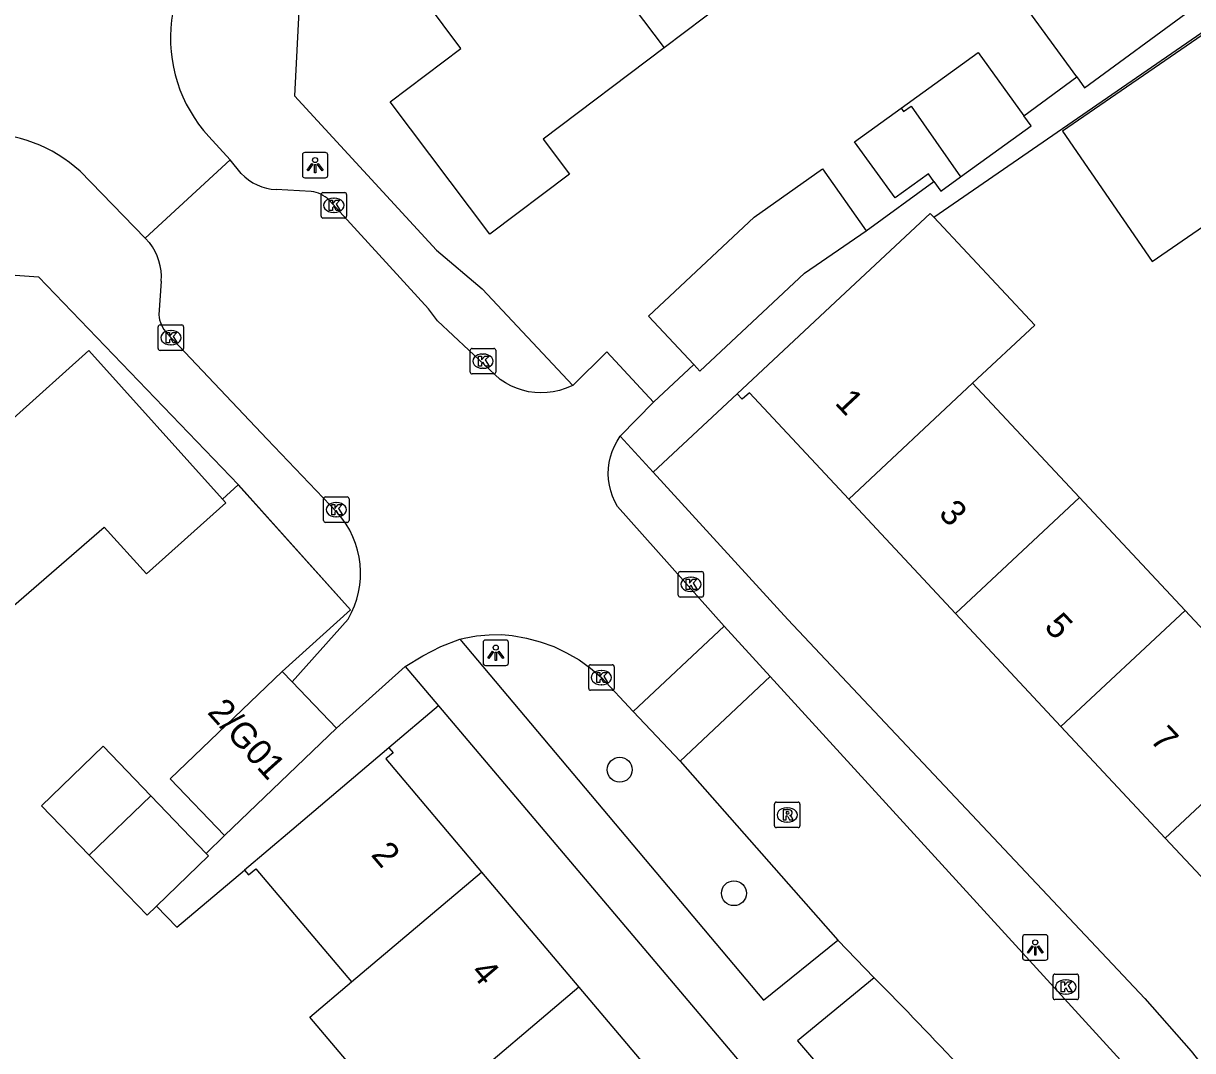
# Model space of a CAD drawing. Extents: x 157466 to 158888, y 383063 to 384677.
# Drawn here: x 158056 to 158101.94, y 383679.09 to 383719.45 of the extents above; entities that cross this region are included whole.
import ezdxf

# ---------------------------------------------------------------- set-up
doc = ezdxf.new("R2010")
doc.units = 0
for name, color, linetype in [('IMGEO_Boom', 7, 'Continuous'), ('IMGEO_Kolk', 7, 'Continuous'), ('IMGEO_Lichtpunt', 7, 'Continuous'), ('IMGEO_Muur', 7, 'Continuous'), ('IMGEO_Pand', 7, 'Continuous'), ('IMGEO_Pand_nummerreeks', 7, 'Continuous'), ('IMGEO_Rijbaan_lokaal_open', 7, 'Continuous'), ('IMGEO_Rioolput', 7, 'Continuous'), ('IMGEO_Voetpad_open', 7, 'Continuous')]:
    doc.layers.add(name, color=color, linetype=linetype)

msp = doc.modelspace()

# ---------------------------------------------------------------- linework, layer by layer
at = {"layer": 'IMGEO_Boom'}
for centre in [(158079.433, 383690.12), (158083.92, 383685.27)]:
    msp.add_circle(centre, 0.489, dxfattribs=at)
at = {"layer": 'IMGEO_Kolk'}
for p, q in [((158067.699, 383711.873), (158067.699, 383712.725)), ((158067.774, 383712.799), (158068.626, 383712.799)), ((158068.7, 383712.725), (158068.7, 383711.873)), ((158068.187, 383712.579), (158068.212, 383712.579)), ((158068.21, 383712.019), (158068.185, 383712.019)), ((158068.626, 383711.799), (158067.774, 383711.799)), ((158061.297, 383706.673), (158061.297, 383707.525)), ((158061.372, 383707.599), (158062.224, 383707.599)), ((158061.785, 383707.379), (158061.81, 383707.379)), ((158062.298, 383707.525), (158062.298, 383706.673)), ((158061.808, 383706.819), (158061.783, 383706.819)), ((158062.224, 383706.599), (158061.372, 383706.599)), ((158073.559, 383705.748), (158073.559, 383706.6)), ((158073.634, 383706.674), (158074.486, 383706.674)), ((158074.047, 383706.454), (158074.072, 383706.454)), ((158074.56, 383706.6), (158074.56, 383705.748)), ((158074.07, 383705.894), (158074.045, 383705.894)), ((158074.486, 383705.674), (158073.634, 383705.674)), ((158067.87, 383700.838), (158068.722, 383700.838)), ((158067.795, 383699.912), (158067.795, 383700.764)), ((158068.283, 383700.618), (158068.308, 383700.618)), ((158068.796, 383700.764), (158068.796, 383699.912)), ((158068.306, 383700.058), (158068.281, 383700.058)), ((158068.722, 383699.838), (158067.87, 383699.838)), ((158081.729, 383696.981), (158081.729, 383697.833)), ((158081.804, 383697.907), (158082.656, 383697.907)), ((158082.217, 383697.687), (158082.242, 383697.687)), ((158082.73, 383697.833), (158082.73, 383696.981)), ((158082.24, 383697.127), (158082.215, 383697.127)), ((158082.656, 383696.907), (158081.804, 383696.907)), ((158078.213, 383693.317), (158078.213, 383694.169)), ((158078.288, 383694.243), (158079.14, 383694.243)), ((158078.701, 383694.023), (158078.726, 383694.023)), ((158079.214, 383694.169), (158079.214, 383693.317)), ((158078.724, 383693.463), (158078.699, 383693.463)), ((158079.14, 383693.243), (158078.288, 383693.243)), ((158096.46, 383681.163), (158096.46, 383682.015)), ((158096.535, 383682.089), (158097.387, 383682.089)), ((158097.461, 383682.015), (158097.461, 383681.163)), ((158096.948, 383681.869), (158096.973, 383681.869)), ((158097.387, 383681.089), (158096.535, 383681.089)), ((158096.971, 383681.309), (158096.946, 383681.309))]:
    msp.add_line(p, q, dxfattribs=at)
for points in [[(158067.699, 383711.873), (158067.699, 383712.725)], [(158067.774, 383712.799), (158068.626, 383712.799)], [(158068.7, 383712.725), (158068.7, 383711.873)], [(158068.02, 383712.499), (158068.143, 383712.499), (158068.143, 383712.348), (158068.273, 383712.499), (158068.437, 383712.499), (158068.291, 383712.348), (158068.444, 383712.099), (158068.292, 383712.099), (158068.207, 383712.263), (158068.143, 383712.196), (158068.143, 383712.099), (158068.02, 383712.099), (158068.02, 383712.499)], [(158068.626, 383711.799), (158067.774, 383711.799)], [(158061.297, 383706.673), (158061.297, 383707.525)], [(158061.372, 383707.599), (158062.224, 383707.599)], [(158061.618, 383707.299), (158061.741, 383707.299), (158061.741, 383707.148), (158061.871, 383707.299), (158062.035, 383707.299), (158061.889, 383707.148), (158062.042, 383706.899), (158061.89, 383706.899), (158061.805, 383707.063), (158061.741, 383706.996), (158061.741, 383706.899), (158061.618, 383706.899), (158061.618, 383707.299)], [(158062.298, 383707.525), (158062.298, 383706.673)], [(158062.224, 383706.599), (158061.372, 383706.599)], [(158073.559, 383705.748), (158073.559, 383706.6)], [(158073.634, 383706.674), (158074.486, 383706.674)], [(158073.88, 383706.374), (158074.003, 383706.374), (158074.003, 383706.223), (158074.133, 383706.374), (158074.297, 383706.374), (158074.151, 383706.223), (158074.304, 383705.974), (158074.152, 383705.974), (158074.067, 383706.138), (158074.003, 383706.071), (158074.003, 383705.974), (158073.88, 383705.974), (158073.88, 383706.374)], [(158074.56, 383706.6), (158074.56, 383705.748)], [(158074.486, 383705.674), (158073.634, 383705.674)], [(158067.87, 383700.838), (158068.722, 383700.838)], [(158067.795, 383699.912), (158067.795, 383700.764)], [(158068.116, 383700.538), (158068.239, 383700.538), (158068.239, 383700.387), (158068.369, 383700.538), (158068.533, 383700.538), (158068.387, 383700.387), (158068.54, 383700.138), (158068.388, 383700.138), (158068.303, 383700.302), (158068.239, 383700.235), (158068.239, 383700.138), (158068.116, 383700.138), (158068.116, 383700.538)], [(158068.796, 383700.764), (158068.796, 383699.912)], [(158068.722, 383699.838), (158067.87, 383699.838)], [(158081.729, 383696.981), (158081.729, 383697.833)], [(158081.804, 383697.907), (158082.656, 383697.907)], [(158082.05, 383697.607), (158082.173, 383697.607), (158082.173, 383697.456), (158082.303, 383697.607), (158082.467, 383697.607), (158082.321, 383697.456), (158082.474, 383697.207), (158082.322, 383697.207), (158082.237, 383697.371), (158082.173, 383697.304), (158082.173, 383697.207), (158082.05, 383697.207), (158082.05, 383697.607)], [(158082.73, 383697.833), (158082.73, 383696.981)], [(158082.656, 383696.907), (158081.804, 383696.907)], [(158078.213, 383693.317), (158078.213, 383694.169)], [(158078.288, 383694.243), (158079.14, 383694.243)], [(158078.534, 383693.943), (158078.657, 383693.943), (158078.657, 383693.792), (158078.787, 383693.943), (158078.951, 383693.943), (158078.805, 383693.792), (158078.958, 383693.543), (158078.806, 383693.543), (158078.721, 383693.707), (158078.657, 383693.64), (158078.657, 383693.543), (158078.534, 383693.543), (158078.534, 383693.943)], [(158079.214, 383694.169), (158079.214, 383693.317)], [(158079.14, 383693.243), (158078.288, 383693.243)], [(158096.46, 383681.163), (158096.46, 383682.015)], [(158096.535, 383682.089), (158097.387, 383682.089)], [(158097.461, 383682.015), (158097.461, 383681.163)], [(158096.781, 383681.789), (158096.904, 383681.789), (158096.904, 383681.638), (158097.034, 383681.789), (158097.198, 383681.789), (158097.052, 383681.638), (158097.205, 383681.389), (158097.053, 383681.389), (158096.968, 383681.553), (158096.904, 383681.486), (158096.904, 383681.389), (158096.781, 383681.389), (158096.781, 383681.789)], [(158097.387, 383681.089), (158096.535, 383681.089)]]:
    msp.add_lwpolyline(points, dxfattribs=at)
for centre, start, end in [((158067.776, 383712.723), 91.552, 178.448), ((158067.776, 383712.723), 91.552, 178.448), ((158068.624, 383712.723), 1.552, 88.448), ((158068.624, 383712.723), 1.552, 88.448), ((158067.776, 383711.875), 181.552, 268.448), ((158067.776, 383711.875), 181.552, 268.448), ((158068.624, 383711.875), 271.552, 358.448), ((158068.624, 383711.875), 271.552, 358.448), ((158061.374, 383707.523), 91.552, 178.448), ((158061.374, 383707.523), 91.552, 178.448), ((158062.222, 383707.523), 1.552, 88.448), ((158062.222, 383707.523), 1.552, 88.448), ((158061.374, 383706.675), 181.552, 268.448), ((158061.374, 383706.675), 181.552, 268.448), ((158062.222, 383706.675), 271.552, 358.448), ((158062.222, 383706.675), 271.552, 358.448), ((158073.636, 383706.598), 91.552, 178.448), ((158073.636, 383706.598), 91.552, 178.448), ((158074.484, 383706.598), 1.552, 88.448), ((158074.484, 383706.598), 1.552, 88.448), ((158073.636, 383705.75), 181.552, 268.448), ((158073.636, 383705.75), 181.552, 268.448), ((158074.484, 383705.75), 271.552, 358.448), ((158074.484, 383705.75), 271.552, 358.448), ((158067.872, 383700.762), 91.552, 178.448), ((158067.872, 383700.762), 91.552, 178.448), ((158068.72, 383700.762), 1.552, 88.448), ((158068.72, 383700.762), 1.552, 88.448), ((158067.872, 383699.914), 181.552, 268.448), ((158067.872, 383699.914), 181.552, 268.448), ((158068.72, 383699.914), 271.552, 358.448), ((158068.72, 383699.914), 271.552, 358.448), ((158081.806, 383697.831), 91.552, 178.448), ((158081.806, 383697.831), 91.552, 178.448), ((158082.654, 383697.831), 1.552, 88.448), ((158082.654, 383697.831), 1.552, 88.448), ((158081.806, 383696.983), 181.552, 268.448), ((158081.806, 383696.983), 181.552, 268.448), ((158082.654, 383696.983), 271.552, 358.448), ((158082.654, 383696.983), 271.552, 358.448), ((158078.29, 383694.167), 91.552, 178.448), ((158078.29, 383694.167), 91.552, 178.448), ((158079.138, 383694.167), 1.552, 88.448), ((158079.138, 383694.167), 1.552, 88.448), ((158078.29, 383693.319), 181.552, 268.448), ((158078.29, 383693.319), 181.552, 268.448), ((158079.138, 383693.319), 271.552, 358.448), ((158079.138, 383693.319), 271.552, 358.448), ((158096.537, 383682.013), 91.552, 178.448), ((158096.537, 383682.013), 91.552, 178.448), ((158097.385, 383682.013), 1.552, 88.448), ((158097.385, 383682.013), 1.552, 88.448), ((158096.537, 383681.165), 181.552, 268.448), ((158096.537, 383681.165), 181.552, 268.448), ((158097.385, 383681.165), 271.552, 358.448), ((158097.385, 383681.165), 271.552, 358.448)]:
    msp.add_arc(centre, 0.0765, start, end, dxfattribs=at)
for centre, major_axis, ratio, start_param, end_param in [((158068.186, 383712.299), (-0.387, 0.002), 0.722429, 4.712389, 7.853982), ((158068.211, 383712.299), (-0.39, 0.002), 0.717154, 1.570796, 4.712389), ((158061.784, 383707.099), (-0.387, 0.002), 0.722429, 4.712389, 7.853982), ((158061.809, 383707.099), (-0.39, 0.002), 0.717154, 1.570796, 4.712389), ((158074.046, 383706.174), (-0.387, 0.002), 0.722429, 4.712389, 7.853982), ((158074.071, 383706.174), (-0.39, 0.002), 0.717154, 1.570796, 4.712389), ((158068.282, 383700.338), (-0.387, 0.002), 0.722429, 4.712389, 7.853982), ((158068.307, 383700.338), (-0.39, 0.002), 0.717154, 1.570796, 4.712389), ((158082.216, 383697.407), (-0.387, 0.002), 0.722429, 4.712389, 7.853982), ((158082.241, 383697.407), (-0.39, 0.002), 0.717154, 1.570796, 4.712389), ((158078.7, 383693.743), (-0.387, 0.002), 0.722429, 4.712389, 7.853982), ((158078.725, 383693.743), (-0.39, 0.002), 0.717154, 1.570796, 4.712389), ((158096.947, 383681.589), (-0.387, 0.002), 0.722429, 4.712389, 7.853982), ((158096.972, 383681.589), (-0.39, 0.002), 0.717154, 1.570796, 4.712389)]:
    msp.add_ellipse(centre, major_axis=major_axis, ratio=ratio, start_param=start_param, end_param=end_param, dxfattribs=at)
at = {"layer": 'IMGEO_Lichtpunt'}
for p, q in [((158066.964, 383714.279), (158066.964, 383713.472)), ((158066.964, 383714.279), (158066.964, 383713.472)), ((158067.866, 383714.374), (158067.058, 383714.374)), ((158067.866, 383714.374), (158067.058, 383714.374)), ((158067.96, 383713.472), (158067.96, 383714.279)), ((158067.96, 383713.472), (158067.96, 383714.279)), ((158067.058, 383713.378), (158067.866, 383713.378)), ((158067.058, 383713.378), (158067.866, 383713.378)), ((158074.062, 383695.121), (158074.062, 383694.314)), ((158074.062, 383695.121), (158074.062, 383694.314)), ((158074.964, 383695.216), (158074.156, 383695.216)), ((158074.964, 383695.216), (158074.156, 383695.216)), ((158075.058, 383694.314), (158075.058, 383695.121)), ((158075.058, 383694.314), (158075.058, 383695.121)), ((158074.156, 383694.22), (158074.964, 383694.22)), ((158074.156, 383694.22), (158074.964, 383694.22)), ((158095.262, 383683.541), (158095.262, 383682.734)), ((158095.262, 383683.541), (158095.262, 383682.734)), ((158096.164, 383683.636), (158095.356, 383683.636)), ((158096.164, 383683.636), (158095.356, 383683.636)), ((158096.258, 383682.734), (158096.258, 383683.541)), ((158096.258, 383682.734), (158096.258, 383683.541)), ((158095.356, 383682.64), (158096.164, 383682.64)), ((158095.356, 383682.64), (158096.164, 383682.64))]:
    msp.add_line(p, q, dxfattribs=at)
for points in [[(158067.338, 383713.943), (158067.377, 383713.915), (158067.189, 383713.653), (158067.151, 383713.68), (158067.338, 383713.943)], [(158067.44, 383713.895), (158067.487, 383713.895), (158067.487, 383713.573), (158067.44, 383713.573), (158067.44, 383713.895)], [(158067.55, 383713.915), (158067.588, 383713.942), (158067.775, 383713.68), (158067.736, 383713.652), (158067.55, 383713.915)], [(158074.436, 383694.785), (158074.475, 383694.757), (158074.287, 383694.495), (158074.249, 383694.522), (158074.436, 383694.785)], [(158074.538, 383694.737), (158074.585, 383694.737), (158074.585, 383694.415), (158074.538, 383694.415), (158074.538, 383694.737)], [(158074.648, 383694.757), (158074.686, 383694.784), (158074.873, 383694.522), (158074.834, 383694.494), (158074.648, 383694.757)], [(158095.636, 383683.205), (158095.675, 383683.177), (158095.487, 383682.915), (158095.449, 383682.942), (158095.636, 383683.205)], [(158095.738, 383683.157), (158095.785, 383683.157), (158095.785, 383682.835), (158095.738, 383682.835), (158095.738, 383683.157)], [(158095.848, 383683.177), (158095.886, 383683.204), (158096.073, 383682.942), (158096.034, 383682.914), (158095.848, 383683.177)]]:
    msp.add_lwpolyline(points, dxfattribs=at)
for centre in [(158067.463, 383714.077), (158074.561, 383694.919), (158095.761, 383683.339)]:
    msp.add_circle(centre, 0.0994, dxfattribs=at)
for centre, start, end in [((158067.058, 383714.279), 90, 180), ((158067.058, 383714.279), 90, 180), ((158067.866, 383714.279), 0, 90), ((158067.866, 383714.279), 0, 90), ((158067.058, 383713.472), 180, 270), ((158067.058, 383713.472), 180, 270), ((158067.866, 383713.472), 270, 0), ((158067.866, 383713.472), 270, 360), ((158074.156, 383695.121), 90, 180), ((158074.156, 383695.121), 90, 180), ((158074.964, 383695.121), 0, 90), ((158074.964, 383695.121), 0, 90), ((158074.156, 383694.314), 180, 270), ((158074.156, 383694.314), 180, 270), ((158074.964, 383694.314), 270, 0), ((158074.964, 383694.314), 270, 360), ((158095.356, 383683.541), 90, 180), ((158095.356, 383683.541), 90, 180), ((158096.164, 383683.541), 0, 90), ((158096.164, 383683.541), 0, 90), ((158095.356, 383682.734), 180, 270), ((158095.356, 383682.734), 180, 270), ((158096.164, 383682.734), 270, 0), ((158096.164, 383682.734), 270, 360)]:
    msp.add_arc(centre, 0.0946, start, end, dxfattribs=at)
at = {"layer": 'IMGEO_Muur'}
for points in [[(158074.025, 383709.017), (158077.584, 383705.224)], [(158063.821, 383700.757), (158064.446, 383701.318)], [(158064.446, 383701.318), (158068.858, 383696.409)], [(158066.165, 383693.981), (158068.858, 383696.409)]]:
    msp.add_lwpolyline(points, dxfattribs=at)
at = {"layer": 'IMGEO_Pand'}
for points in [[(158081.173, 383718.488), (158076.419, 383714.899), (158077.455, 383713.526), (158074.328, 383711.165), (158070.408, 383716.358), (158073.195, 383718.462), (158071.797, 383720.314), (158072.106, 383720.547), (158072.365, 383720.203), (158077.158, 383723.821)], [(158077.158, 383723.821), (158081.173, 383718.488)], [(158097.388, 383717.341), (158095.503, 383719.92), (158099.684, 383722.976)], [(158097.388, 383717.341), (158097.697, 383716.918), (158101.878, 383719.973), (158099.684, 383722.976)], [(158085.977, 383722.114), (158081.173, 383718.488)], [(158102.524, 383719.13), (158096.827, 383715.205), (158100.352, 383710.087), (158103.342, 383712.147)], [(158090.491, 383716.118), (158093.515, 383718.301), (158095.307, 383715.819)], [(158091.776, 383713.239), (158091.562, 383713.535), (158090.251, 383712.589), (158088.659, 383714.795), (158090.491, 383716.118)], [(158090.491, 383716.118), (158090.589, 383715.988), (158090.888, 383716.196), (158092.816, 383713.412)], [(158092.816, 383713.412), (158095.596, 383715.419), (158095.307, 383715.819)], [(158082.342, 383706.039), (158080.56, 383707.946), (158084.714, 383711.826), (158087.401, 383713.728), (158089.119, 383711.297)], [(158091.776, 383713.239), (158092.05, 383712.859), (158092.816, 383713.412)], [(158091.772, 383711.829), (158091.632, 383711.98), (158089.485, 383709.977), (158087.7, 383708.309), (158084.045, 383704.896)], [(158093.299, 383705.306), (158095.737, 383707.585), (158091.772, 383711.829)], [(158082.342, 383706.039), (158082.578, 383705.786), (158086.698, 383709.634), (158089.119, 383711.297)], [(158054.533, 383695.63), (158059.181, 383699.651), (158060.834, 383697.812), (158063.954, 383700.608), (158063.821, 383700.757), (158058.573, 383706.595), (158055.594, 383703.926), (158054.197, 383705.48), (158053.956, 383705.264), (158054.22, 383704.97), (158049.774, 383701.125)], [(158088.43, 383700.755), (158084.527, 383704.934), (158084.25, 383704.676), (158084.045, 383704.896)], [(158088.43, 383700.755), (158093.299, 383705.306)], [(158097.496, 383700.816), (158093.299, 383705.306)], [(158092.625, 383696.263), (158097.496, 383700.816)], [(158101.644, 383696.379), (158097.496, 383700.816)], [(158092.625, 383696.263), (158088.43, 383700.755)], [(158096.77, 383691.825), (158092.625, 383696.263)], [(158101.644, 383696.379), (158096.77, 383691.825)], [(158105.745, 383691.992), (158101.644, 383696.379)], [(158066.165, 383693.981), (158061.766, 383689.76), (158063.904, 383687.532)], [(158066.165, 383693.981), (158066.557, 383693.572)], [(158066.557, 383693.572), (158068.304, 383691.753)], [(158063.904, 383687.532), (158068.304, 383691.753)], [(158100.869, 383687.435), (158096.77, 383691.825)], [(158100.869, 383687.435), (158105.745, 383691.992)], [(158061.011, 383689.092), (158059.139, 383691.042), (158056.713, 383688.701), (158058.585, 383686.761)], [(158070.36, 383690.983), (158066.544, 383687.753), (158064.686, 383686.181)], [(158070.36, 383690.983), (158070.525, 383690.787), (158070.237, 383690.543), (158074, 383686.097)], [(158058.585, 383686.761), (158061.011, 383689.092)], [(158063.179, 383686.834), (158061.011, 383689.092)], [(158105.049, 383682.96), (158100.869, 383687.435)], [(158058.585, 383686.761), (158060.862, 383684.402), (158061.232, 383684.759)], [(158063.179, 383686.834), (158063.277, 383686.732), (158061.232, 383684.759)], [(158064.686, 383686.181), (158064.846, 383685.992), (158065.131, 383686.233), (158068.897, 383681.783)], [(158068.897, 383681.783), (158074, 383686.097)], [(158074, 383686.097), (158077.829, 383681.572)], [(158072.726, 383677.258), (158071.078, 383675.88), (158067.259, 383680.398), (158068.897, 383681.783)], [(158077.829, 383681.572), (158072.726, 383677.258)], [(158077.829, 383681.572), (158081.783, 383676.9)]]:
    msp.add_lwpolyline(points, dxfattribs=at)
at = {"layer": 'IMGEO_Rijbaan_lokaal_open'}
for points in [[(158064.124, 383714.09), (158063.283, 383715.004)], [(158060.786, 383711.008), (158064.124, 383714.09)], [(158064.56, 383713.552), (158064.124, 383714.09)], [(158058.232, 383713.633), (158060.786, 383711.008)], [(158067.311, 383712.842), (158065.937, 383712.913)], [(158077.584, 383705.224), (158077.52, 383705.193), (158077.295, 383705.098), (158077.062, 383705.024), (158076.823, 383704.971), (158076.581, 383704.939), (158076.336, 383704.929), (158076.092, 383704.941), (158075.85, 383704.975), (158075.612, 383705.03), (158075.379, 383705.107), (158075.155, 383705.203), (158074.94, 383705.32), (158074.736, 383705.455), (158072.279, 383707.764), (158071.914, 383708.233), (158068.01, 383712.506)], [(158060.786, 383711.008), (158060.962, 383710.83)], [(158061.42, 383709.32), (158061.322, 383707.998)], [(158061.65, 383707.256), (158065.583, 383703.103), (158068.326, 383700.226)], [(158077.584, 383705.224), (158078.924, 383706.544), (158080.76, 383704.561)], [(158079.451, 383703.221), (158080.76, 383704.561)], [(158083.532, 383695.764), (158079.347, 383700.464), (158079.239, 383700.662), (158079.15, 383700.868), (158079.079, 383701.081), (158079.028, 383701.299), (158078.996, 383701.522), (158078.985, 383701.746), (158078.993, 383701.97), (158079.022, 383702.193), (158079.07, 383702.412), (158079.138, 383702.627), (158079.224, 383702.834), (158079.329, 383703.032), (158079.451, 383703.221)], [(158068.759, 383696.04), (158066.557, 383693.572)], [(158079.964, 383692.414), (158083.532, 383695.764)], [(158085.347, 383693.787), (158083.532, 383695.764)], [(158073.153, 383695.248), (158073.321, 383695.29), (158073.811, 383695.381), (158074.307, 383695.428), (158074.806, 383695.43), (158075.212, 383695.391), (158075.767, 383695.295), (158076.31, 383695.15), (158076.838, 383694.957), (158077.347, 383694.717), (158077.833, 383694.433), (158078.291, 383694.107), (158078.718, 383693.741), (158079.964, 383692.414)], [(158071.006, 383694.181), (158071.692, 383694.602), (158072.408, 383694.958), (158073.153, 383695.248)], [(158068.304, 383691.753), (158071.006, 383694.181)], [(158085.347, 383693.787), (158081.806, 383690.454)], [(158117.353, 383655.647), (158105.457, 383671.597), (158103.101, 383674.336), (158085.347, 383693.787)], [(158081.806, 383690.454), (158079.964, 383692.414)], [(158081.806, 383690.454), (158088.008, 383683.429)], [(158088.008, 383683.429), (158089.434, 383681.946)]]:
    msp.add_lwpolyline(points, dxfattribs=at)
for centre, radius, start, end in [((158067.516, 383718.875), 5.736, 123.6171, 222.4461), ((158054.425, 383709.481), 5.633, 47.4872, 91.4484), ((158066.03, 383714.916), 2.005, 222.8619, 267.3506), ((158067.148, 383711.608), 1.245, 46.1731, 82.4809), ((158059.209, 383709.474), 2.216, 356.0163, 37.73), ((158062.546, 383708.096), 1.228, 184.5559, 223.1396), ((158065.721, 383697.841), 3.531, 329.3328, 42.4785), ((157977.199, 383570.714), 158.017, 42.92697, 44.74268)]:
    msp.add_arc(centre, radius, start, end, dxfattribs=at)
at = {"layer": 'IMGEO_Rioolput'}
for p, q in [((158085.588, 383688.847), (158086.44, 383688.847)), ((158085.513, 383687.921), (158085.513, 383688.773)), ((158086.001, 383688.627), (158086.026, 383688.627)), ((158086.514, 383688.773), (158086.514, 383687.921)), ((158086.024, 383688.067), (158085.999, 383688.067)), ((158086.44, 383687.847), (158085.588, 383687.847))]:
    msp.add_line(p, q, dxfattribs=at)
for points in [[(158085.588, 383688.847), (158086.44, 383688.847)], [(158085.513, 383687.921), (158085.513, 383688.773)], [(158086.102, 383688.545), (158085.85, 383688.547), (158085.85, 383688.147)], [(158086.028, 383688.466), (158085.974, 383688.466), (158085.974, 383688.385)], [(158085.974, 383688.385), (158086.026, 383688.385)], [(158086.514, 383688.773), (158086.514, 383687.921)], [(158085.85, 383688.147), (158085.974, 383688.147), (158085.974, 383688.309), (158085.985, 383688.309)], [(158086.032, 383688.28), (158086.103, 383688.147), (158086.243, 383688.147), (158086.178, 383688.273)], [(158086.44, 383687.847), (158085.588, 383687.847)]]:
    msp.add_lwpolyline(points, dxfattribs=at)
for centre, radius, start, end in [((158085.59, 383688.771), 0.0765, 91.552, 178.448), ((158085.59, 383688.771), 0.0765, 91.552, 178.448), ((158086.438, 383688.771), 0.0765, 1.552, 88.448), ((158086.438, 383688.771), 0.0765, 1.552, 88.448), ((158086.01, 383688.574), 0.19, 274.7715, 282.9687), ((158086.034, 383688.37), 0.0964, 77.0061, 93.1865), ((158086.048, 383688.427), 0.0378, 276.6634, 79.6772), ((158086.101, 383688.435), 0.109, 350.3612, 89.416), ((158086.099, 383688.435), 0.112, 277.5842, 350.9817), ((158085.59, 383687.923), 0.0765, 181.552, 268.448), ((158085.59, 383687.923), 0.0765, 181.552, 268.448), ((158085.984, 383688.256), 0.0533, 26.0293, 88.6989), ((158086.083, 383688.22), 0.108, 29.5134, 73.7905), ((158086.438, 383687.923), 0.0765, 271.552, 358.448), ((158086.438, 383687.923), 0.0765, 271.552, 358.448)]:
    msp.add_arc(centre, radius, start, end, dxfattribs=at)
for centre, major_axis, ratio, start_param, end_param in [((158086, 383688.347), (-0.387, 0.002), 0.722429, 4.712389, 7.853982), ((158086.025, 383688.347), (-0.39, 0.002), 0.717154, 1.570796, 4.712389)]:
    msp.add_ellipse(centre, major_axis=major_axis, ratio=ratio, start_param=start_param, end_param=end_param, dxfattribs=at)
at = {"layer": 'IMGEO_Voetpad_open'}
for points in [[(158089.464, 383737.55), (158066.847, 383720.445), (158066.656, 383716.599), (158072.237, 383710.535), (158074.025, 383709.017), (158077.584, 383705.224)], [(158091.772, 383711.829), (158102.474, 383719.202), (158102.524, 383719.13)], [(158095.307, 383715.819), (158097.388, 383717.341)], [(158089.119, 383711.297), (158091.776, 383713.239)], [(158052.35, 383709.789), (158056.595, 383709.482), (158064.449, 383701.315), (158068.858, 383696.409), (158066.165, 383693.981)], [(158080.76, 383704.561), (158082.342, 383706.039)], [(158084.045, 383704.896), (158080.741, 383701.811)], [(158080.741, 383701.811), (158079.451, 383703.221)], [(158080.741, 383701.811), (158086.038, 383696.025), (158100.067, 383681.132), (158101.887, 383679.058), (158105.261, 383674.8)], [(158073.153, 383695.248), (158085.078, 383681.064), (158088.008, 383683.429)], [(158071.006, 383694.181), (158072.313, 383692.636)], [(158072.313, 383692.636), (158070.36, 383690.983)], [(158072.313, 383692.636), (158095.722, 383664.977), (158093.805, 383663.256)], [(158063.904, 383687.532), (158063.179, 383686.834)], [(158061.232, 383684.759), (158062.029, 383683.933), (158064.686, 383686.181)], [(158089.434, 383681.946), (158086.414, 383679.474), (158089.769, 383675.56), (158092.902, 383678.334)]]:
    msp.add_lwpolyline(points, dxfattribs=at)

# ---------------------------------------------------------------- texts
at = {"layer": 'IMGEO_Pand_nummerreeks'}
for s, rotation, p in [('1', 313.0576, (158087.851, 383704.513)), ('3', 313.0559, (158091.925, 383700.155)), ('5', 313.0559, (158096.075, 383695.712)), ('2/G01', 311.9872, (158063.198, 383692.361)), ('7', 313.0559, (158100.226, 383691.27)), ('2', 310.2167, (158069.63, 383686.767)), ('4', 310.2167, (158073.539, 383682.144))]:
    msp.add_text(s, height=1, rotation=rotation, dxfattribs=at).set_placement(p)

doc.saveas('drawing.dxf')
